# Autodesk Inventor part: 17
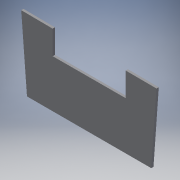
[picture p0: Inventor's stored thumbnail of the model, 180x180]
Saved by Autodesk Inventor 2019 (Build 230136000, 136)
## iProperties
Created: 2019-01
Part Number: 17
Material: Generic
Document SubType Name: Modeling
Designer: Guy Link
Density: 1 g/cm^3
Appearance: Default
Author: Guy Link
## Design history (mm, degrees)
sketch "Sketch1"
  geometry: L1 (-67.206, -30.65)-(-75.203, 69.047); L2 (-75.203, 69.047)-(-31.588, 68.627); L3 (-31.588, 68.627)-(-31.55, 35.508); L4 (-31.55, 35.508)-(70.056, 35.738); L5 (70.056, 35.738)-(69.802, 68.953); L6 (69.802, 68.953)-(112.635, 68.735); L7 (112.635, 68.735)-(105.311, -30.65); L8 (105.311, -30.65)-(-67.206, -30.65); 1 further point
  constraints: 16 end point
extrude "Extrusion1" new body sketch "Sketch1" distance "d0" = 3.175; taper "d1" = 0 deg
body "Solid1"
